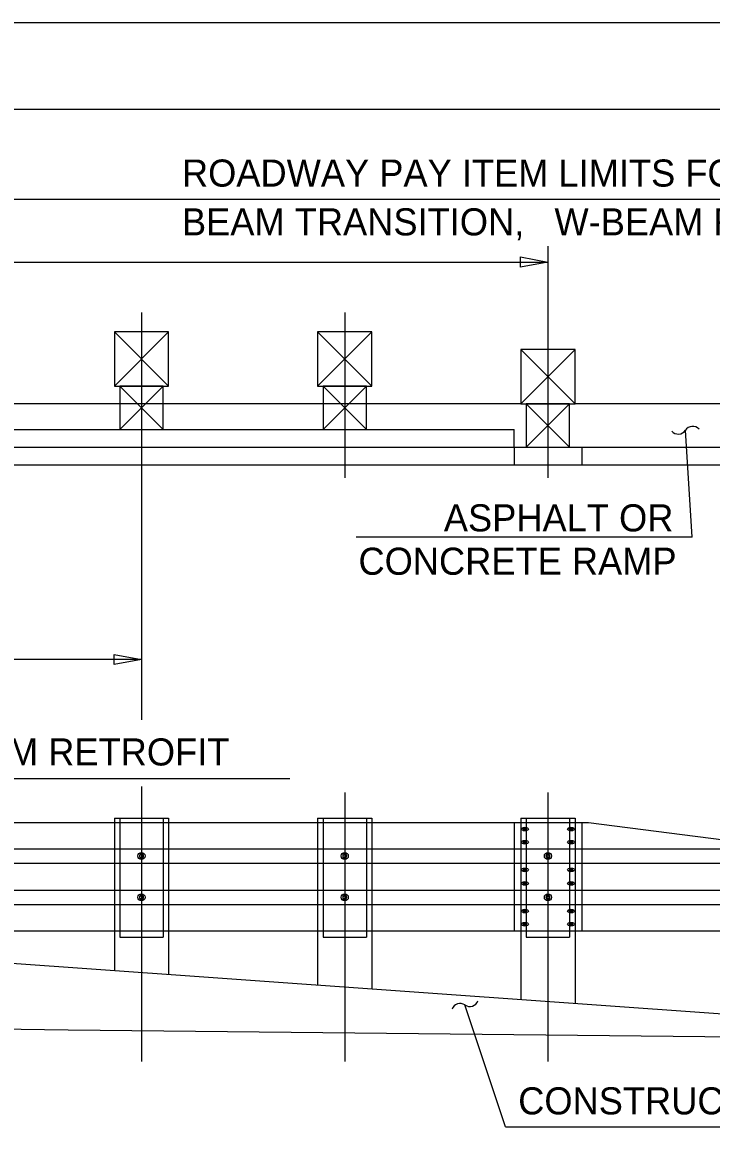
# Model space of a CAD drawing. Extents: x 0 to 22.7, y 0 to 15.7.
# Drawn here: x 14.849 to 17.498, y 10.354 to 14.667 of the extents above; entities that cross this region are included whole.
import ezdxf

# ---------------------------------------------------------------- set-up
doc = ezdxf.new("R2010")
doc.units = 0
for name, color, linetype in [('BORDER_ANNO_Cutsheet', 7, 'Continuous'), ('BRDG_ANNO_Anno-Sheet', 7, 'Continuous'), ('BRDG_ANNO_General-Notes', 7, 'Continuous'), ('BRDG_BASE_Dtlctrln', 7, 'Continuous'), ('BRDG_BASE_Phtline', 7, 'Continuous')]:
    doc.layers.add(name, color=color, linetype=linetype)

msp = doc.modelspace()

# ---------------------------------------------------------------- linework, layer by layer
at = {"layer": 'BORDER_ANNO_Cutsheet'}
msp.add_lwpolyline([(0, 14.6667), (22.6667, 14.6667), (22.6667, 0), (0, 0)], close=True, dxfattribs=at)
at = {"layer": 'BRDG_ANNO_Anno-Sheet'}
msp.add_lwpolyline([(1, 14.3333), (22.3333, 14.3333), (22.3333, 0.3333), (1, 0.3333)], close=True, dxfattribs=at)
at = {"layer": 'BRDG_ANNO_General-Notes'}
for p, q in [((20.252, 13.9864), (14.4561, 13.9864)), ((16.764, 13.7259), (16.764, 13.7653)), ((16.764, 13.7653), (16.869, 13.7456)), ((11.488, 13.7456), (16.869, 13.7456)), ((16.869, 13.7456), (16.764, 13.7259)), ((17.4239, 12.6886), (17.3972, 13.0994)), ((17.4239, 12.6886), (16.1316, 12.6886)), ((15.3065, 12.2181), (13.744, 12.2181)), ((15.2015, 12.1984), (15.2015, 12.2378)), ((15.2015, 12.2378), (15.3065, 12.2181)), ((15.3065, 12.2181), (15.2015, 12.1984)), ((16.7052, 10.4213), (16.5499, 10.8902)), ((16.7052, 10.4213), (19.9203, 10.4213))]:
    msp.add_line(p, q, dxfattribs=at)
msp.add_lwpolyline([(14.0208, 11.7608), (15.8765, 11.7608)], dxfattribs=at)
for centre, start, end in [((17.4247, 13.0815), 40.5767, 146.8369), ((17.3698, 13.1174), 220.5767, 326.8369), ((16.5312, 10.8632), 55.1987, 161.4589), ((16.5686, 10.9171), 235.1987, 341.4589)]:
    msp.add_arc(centre, 0.0328, start, end, dxfattribs=at)
at = {"layer": 'BRDG_BASE_Dtlctrln'}
for p, q in [((16.869, 13.8068), (16.869, 12.9157)), ((15.3065, 13.5521), (15.3065, 11.9859)), ((16.0877, 13.5521), (16.0877, 12.9157)), ((15.3065, 11.7305), (15.3065, 10.6736)), ((16.0877, 11.7074), (16.0877, 10.6736)), ((16.869, 11.7074), (16.869, 10.6736))]:
    msp.add_line(p, q, dxfattribs=at)
at = {"layer": 'BRDG_BASE_Phtline'}
for p, q in [((15.2023, 13.2689), (15.4106, 13.4772)), ((15.4106, 13.2689), (15.2023, 13.4772)), ((15.9835, 13.2689), (16.1919, 13.4772)), ((16.1919, 13.2689), (15.9835, 13.4772)), ((16.7648, 13.2011), (16.9731, 13.4095)), ((16.9731, 13.2011), (16.7648, 13.4095)), ((15.2231, 13.1022), (15.3898, 13.2689)), ((15.3898, 13.1022), (15.2231, 13.2689)), ((16.0044, 13.1022), (16.171, 13.2689)), ((16.171, 13.1022), (16.0044, 13.2689)), ((15.0244, 13.2011), (14.4614, 13.2011)), ((16.7648, 13.2011), (15.0244, 13.2011)), ((16.7856, 13.0345), (16.9523, 13.2011)), ((16.9523, 13.0345), (16.7856, 13.2011)), ((17.546, 13.2011), (16.9731, 13.2011)), ((11.6882, 13.1022), (16.7387, 13.1022)), ((16.7387, 13.0345), (16.7387, 13.1022)), ((11.6882, 13.0345), (16.7387, 13.0345)), ((16.7387, 13.0345), (16.7387, 12.9668)), ((16.7387, 13.0345), (21.8499, 13.0345)), ((16.9992, 13.0345), (16.9992, 12.9668)), ((11.6882, 12.9668), (16.7387, 12.9668)), ((16.7387, 12.9668), (21.8499, 12.9668)), ((15.2023, 11.6087), (15.4106, 11.6087)), ((15.2023, 11.6087), (15.2023, 11.5918)), ((15.2231, 11.6087), (15.2231, 11.5918)), ((15.3898, 11.6087), (15.3898, 11.5918)), ((15.4106, 11.6087), (15.4106, 11.5918)), ((15.9835, 11.6087), (16.1919, 11.6087)), ((15.9835, 11.6087), (15.9835, 11.5918)), ((16.0044, 11.6087), (16.0044, 11.5918)), ((16.171, 11.6087), (16.171, 11.5918)), ((16.1919, 11.6087), (16.1919, 11.5918)), ((16.7648, 11.6087), (16.9731, 11.6087)), ((16.7648, 11.6087), (16.7648, 11.5918)), ((16.7856, 11.6087), (16.7856, 11.5918)), ((16.9523, 11.6087), (16.9523, 11.5918)), ((16.9731, 11.6087), (16.9731, 11.5918)), ((11.6882, 11.5918), (16.7387, 11.5918)), ((15.2023, 11.5918), (15.2023, 11.1751)), ((15.2231, 11.5918), (15.2231, 11.1751)), ((15.3898, 11.5918), (15.3898, 11.1751)), ((15.4106, 11.5918), (15.4106, 11.1751)), ((15.9835, 11.5918), (15.9835, 11.1751)), ((16.0044, 11.5918), (16.0044, 11.1751)), ((16.171, 11.5918), (16.171, 11.1751)), ((16.1919, 11.5918), (16.1919, 11.1751)), ((16.7387, 11.5918), (16.7387, 11.1751)), ((16.7387, 11.5918), (17.0252, 11.5918)), ((16.7648, 11.5918), (16.7648, 11.1751)), ((16.7856, 11.5918), (16.7856, 11.1751)), ((16.9523, 11.5918), (16.9523, 11.1751)), ((16.9731, 11.5918), (16.9731, 11.1751)), ((16.9992, 11.5918), (16.9992, 11.1751)), ((17.0252, 11.5918), (18.2752, 11.4303)), ((11.6882, 11.4904), (16.7387, 11.4904)), ((16.7387, 11.4904), (16.9992, 11.4904)), ((16.9992, 11.4904), (17.8105, 11.4904)), ((11.6882, 11.4354), (16.7387, 11.4354)), ((16.7387, 11.4354), (16.9992, 11.4354)), ((16.9992, 11.4354), (18.2359, 11.4354)), ((11.6882, 11.3315), (16.7387, 11.3315)), ((16.7387, 11.3315), (16.9992, 11.3315)), ((16.9992, 11.3315), (18.3012, 11.3315)), ((11.6882, 11.2766), (16.7387, 11.2766)), ((16.7387, 11.2766), (16.9992, 11.2766)), ((16.9992, 11.2766), (18.3012, 11.2766)), ((11.6882, 11.1751), (16.7387, 11.1751)), ((15.2023, 11.1751), (15.2023, 11.0229)), ((15.2231, 11.1751), (15.2231, 11.1504)), ((15.3898, 11.1751), (15.3898, 11.1504)), ((15.4106, 11.1751), (15.4106, 11.0081)), ((15.9835, 11.1751), (15.9835, 10.9672)), ((16.0044, 11.1751), (16.0044, 11.1504)), ((16.171, 11.1751), (16.171, 11.1504)), ((16.1919, 11.1751), (16.1919, 10.9524)), ((16.7387, 11.1751), (16.9992, 11.1751)), ((16.7648, 11.1751), (16.7648, 10.9115)), ((16.7856, 11.1751), (16.7856, 11.1504)), ((16.9523, 11.1751), (16.9523, 11.1504)), ((16.9731, 11.1751), (16.9731, 10.8967)), ((16.9992, 11.1751), (18.3012, 11.1751)), ((15.2231, 11.1504), (15.3898, 11.1504)), ((16.0044, 11.1504), (16.171, 11.1504)), ((16.7856, 11.1504), (16.9523, 11.1504)), ((14.4561, 11.0761), (15.0244, 11.0356)), ((15.0244, 11.0356), (18.3273, 10.8001)), ((15.0244, 10.794), (14.4561, 10.8001)), ((18.3273, 10.7584), (15.0244, 10.794))]:
    msp.add_line(p, q, dxfattribs=at)
for points in [[(15.2023, 13.2689), (15.4106, 13.2689), (15.4106, 13.4772), (15.2023, 13.4772)], [(15.9835, 13.2689), (16.1919, 13.2689), (16.1919, 13.4772), (15.9835, 13.4772)], [(16.7648, 13.2011), (16.9731, 13.2011), (16.9731, 13.4095), (16.7648, 13.4095)], [(15.2231, 13.1022), (15.3898, 13.1022), (15.3898, 13.2689), (15.2231, 13.2689)], [(16.0044, 13.1022), (16.171, 13.1022), (16.171, 13.2689), (16.0044, 13.2689)], [(16.7856, 13.0345), (16.9523, 13.0345), (16.9523, 13.2011), (16.7856, 13.2011)]]:
    msp.add_lwpolyline(points, close=True, dxfattribs=at)
for centre, radius in [((15.3064, 11.4629), 0.0137), ((16.0877, 11.4629), 0.0137), ((16.8689, 11.4629), 0.0137), ((15.3064, 11.4629), 0.00651), ((16.0877, 11.4629), 0.00651), ((16.8689, 11.4629), 0.00651), ((15.3064, 11.304), 0.0137), ((15.3064, 11.304), 0.00651), ((16.0877, 11.304), 0.0137), ((16.0877, 11.304), 0.00651), ((16.8689, 11.304), 0.0137), ((16.8689, 11.304), 0.00651)]:
    msp.add_circle(centre, radius, dxfattribs=at)
for centre, major_axis, ratio in [((16.7804, 11.5664), (0.0137, 0), 0.5), ((16.7804, 11.5664), (0.00651, 0), 0.75), ((16.7804, 11.5664), (0.00651, 0), 0.5), ((16.9575, 11.5664), (0.0137, 0), 0.5), ((16.9575, 11.5664), (0.00651, 0), 0.75), ((16.9575, 11.5664), (0.00651, 0), 0.5), ((16.7804, 11.5157), (0.0137, 0), 0.5), ((16.7804, 11.5157), (0.00651, 0), 0.75), ((16.7804, 11.5157), (0.00651, 0), 0.5), ((16.9575, 11.5157), (0.0137, 0), 0.5), ((16.9575, 11.5157), (0.00651, 0), 0.75), ((16.9575, 11.5157), (0.00651, 0), 0.5), ((15.3064, 11.4629), (0, 0.00977), 0.666667), ((16.0877, 11.4629), (0, 0.00977), 0.666667), ((16.8689, 11.4629), (0, 0.00977), 0.666667), ((16.7804, 11.4094), (0.0137, 0), 0.5), ((16.7804, 11.4094), (-0.00651, 0), 0.75), ((16.7804, 11.4094), (0.00651, 0), 0.5), ((16.9575, 11.4094), (0.0137, 0), 0.5), ((16.9575, 11.4094), (-0.00651, 0), 0.75), ((16.9575, 11.4094), (0.00651, 0), 0.5), ((16.7804, 11.3575), (0.0137, 0), 0.5), ((16.7804, 11.3575), (-0.00651, 0), 0.75), ((16.7804, 11.3575), (0.00651, 0), 0.5), ((16.9575, 11.3575), (0.0137, 0), 0.5), ((16.9575, 11.3575), (-0.00651, 0), 0.75), ((16.9575, 11.3575), (0.00651, 0), 0.5), ((15.3064, 11.304), (0, 0.00977), 0.666667), ((16.0877, 11.304), (0, 0.00977), 0.666667), ((16.8689, 11.304), (0, 0.00977), 0.666667), ((16.7804, 11.2512), (0.0137, 0), 0.5), ((16.9575, 11.2512), (0.0137, 0), 0.5), ((16.7804, 11.2512), (-0.00651, 0), 0.75), ((16.7804, 11.2512), (0.00651, 0), 0.5), ((16.9575, 11.2512), (-0.00651, 0), 0.75), ((16.9575, 11.2512), (0.00651, 0), 0.5), ((16.7804, 11.2005), (0.0137, 0), 0.5), ((16.7804, 11.2005), (-0.00651, 0), 0.75), ((16.7804, 11.2005), (0.00651, 0), 0.5), ((16.9575, 11.2005), (0.0137, 0), 0.5), ((16.9575, 11.2005), (-0.00651, 0), 0.75), ((16.9575, 11.2005), (0.00651, 0), 0.5)]:
    msp.add_ellipse(centre, major_axis=major_axis, ratio=ratio, dxfattribs=at)

# ---------------------------------------------------------------- texts
at = {"layer": 'BRDG_ANNO_General-Notes'}
for s, height, p in [('ROADWAY PAY ITEM LIMITS FOR POSTS OFF BRIDGE,   THRIE', 0.104167, (15.4621, 14.0357)), ('BEAM TRANSITION,   W-BEAM RAIL,   & CONC/ASPH RAMP', 0.104167, (15.4621, 13.8482)), ('ASPHALT OR', 0.10417, (16.4687, 12.7104)), ('CONCRETE RAMP', 0.104167, (16.1406, 12.5437)), ('THRIE BEAM RETROFIT', 0.104167, (14.0579, 11.8107)), ('CONSTRUCT ASPHALT OR CONCRETE RAMP', 0.104167, (16.7546, 10.4696))]:
    msp.add_text(s, height=height, dxfattribs=at).set_placement(p)

doc.saveas('drawing.dxf')
